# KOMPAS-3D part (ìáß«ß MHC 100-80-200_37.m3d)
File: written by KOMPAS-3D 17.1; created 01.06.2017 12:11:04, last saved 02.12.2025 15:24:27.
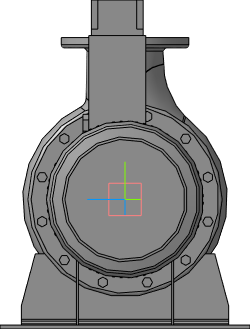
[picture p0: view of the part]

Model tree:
1. Операция без истории:2

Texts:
  ООО АДЛ ГРУПП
